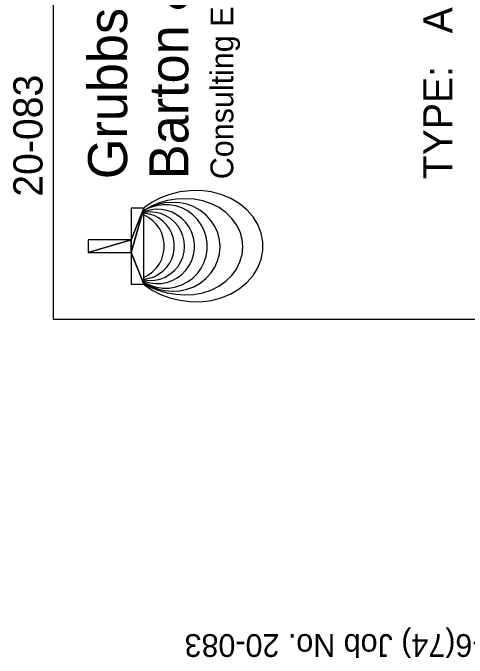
# Model space of a CAD drawing. Extents: x 1313964 to 1316843, y 2087046 to 2096619.
# Drawn here: x 1314172.79 to 1314180.68, y 2089867.54 to 2089878.76 of the extents above; entities that cross this region are included whole.
import ezdxf

# ---------------------------------------------------------------- set-up
doc = ezdxf.new("R2010")
doc.units = 0
doc.layers.add('B-Sub-Contour', color=7, linetype='Continuous')
doc.layers.add('Default', color=7, linetype='Continuous')

# ---------------------------------------------------------------- blocks, each defined once
blk = doc.blocks.new('DGRFC_GGHLOGO')
at = {"layer": 'Default'}
for points in [[(371581.68, 791230.32), (371581.68, 1050310.32), (295381.68, 1050310.32), (371581.68, 791230.32)], [(371581.68, 791230.32), (295381.68, 1050310.32), (295381.68, 791230.32), (371581.68, 791230.32)], [(295381.68, 791230.32), (104881.68, 791230.32), (104881.68, 715030.32), (295381.68, 791230.32)], [(295381.68, 791230.32), (104881.68, 715030.32), (562081.68, 715030.32), (295381.68, 791230.32)], [(295381.68, 791230.32), (562081.68, 715030.32), (371581.68, 791230.32), (295381.68, 791230.32)], [(562081.68, 715030.32), (562081.68, 791230.32), (371581.68, 791230.32), (562081.68, 715030.32)]]:
    blk.add_lwpolyline(points, close=True, dxfattribs=at)
for points in [[(105216.96, 715030.32), (100004.88, 709757.28), (68915.28, 666170.88), (42854.88, 615848.4), (22494.24, 560009.04), (8351.52, 500115.84), (792.48, 437662.32), (0, 374202.96), (7802.88, 311353.2), (23439.12, 250698), (46847.76, 193791.84), (77510.64, 142006.32), (114635.28, 96713.04), (157246.32, 59039.76), (204337.92, 29900.88), (254660.4, 10058.4), (306994.56, 0), (359968.8, 0), (412302.96, 10058.4), (462625.44, 29900.88), (509717.04, 59039.76), (552328.08, 96713.04), (589452.72, 142006.32), (620115.6, 193791.84), (643524.24, 250698), (659160.48, 311353.2), (666963.36, 374202.96), (666170.88, 437662.32), (658611.84, 500115.84), (644469.12, 560009.04), (624108.48, 615848.4), (598048.08, 666170.88), (566958.48, 709757.28), (561746.4, 715030.32)], [(111587.28, 715030.32), (108691.68, 711311.76), (85770.72, 670895.28), (67177.92, 625266.72), (53400.96, 575584.32), (44744.64, 523097.76), (41422.32, 469087.2), (42702.48, 414924.24), (52760.88, 362010.96), (69738.24, 311597.04), (93238.32, 264993.12), (122651.52, 223387.92), (157246.32, 187756.8), (196169.28, 159075.12), (238414.56, 137982.96), (282976.32, 125089.92), (328665.84, 120639.84), (374385.84, 124815.6), (419008.56, 137464.8), (461345.28, 158282.64), (500390.16, 186720.48), (535137.36, 222138.24), (564733.44, 263591.04), (588416.4, 310042.56), (605637.6, 360334.56), (615909.36, 413217.36), (618195.36, 467349.84), (615055.92, 521360.4), (606582.48, 573938.4), (592927.44, 623742.72), (574487.04, 669523.68), (551718.48, 710123.04), (547908.48, 715030.32)], [(113477.04, 715030.32), (111434.88, 712226.16), (91531.44, 674613.84), (76748.64, 633618.24), (67421.76, 590275.68), (63825.12, 545683.44), (65227.2, 500969.28), (74462.64, 457260.96), (90098.88, 415625.28), (111770.16, 377098.56), (138927.84, 342717.12), (170870.88, 313273.44), (206837.28, 289560), (245882.16, 272155.92), (287030.16, 261457.44), (329031.6, 257799.84), (371520.72, 261244.08), (412729.68, 271698.72), (451866, 288889.44), (487923.84, 312420), (520019.28, 341680.8), (547329.36, 375940.32), (569183.52, 414314.64), (585033.12, 455889.36), (594451.44, 499567.2), (596463.12, 544250.88), (593049.36, 588873.6), (583905.36, 632246.64), (569305.44, 673333.68), (549554.4, 711067.92), (546658.8, 715030.32)], [(117957.6, 715030.32), (116220.24, 712561.44), (98968.56, 677509.44), (87386.16, 640201.92), (81747.36, 601522.8), (82174.08, 562477.92), (88696.8, 523951.2), (101071.68, 486887.52), (119085.36, 452231.76), (142250.16, 420776.4), (170047.92, 393283.44), (201747.12, 370453.92), (236616.24, 352836.48), (273801.84, 340857.84), (312389.52, 334792.32), (351464.88, 334792.32), (390052.56, 340857.84), (427238.16, 352836.48), (462107.28, 370453.92), (493806.48, 393283.44), (521573.76, 420776.4), (544769.04, 452231.76), (562752.24, 486887.52), (575157.6, 523951.2), (581649.84, 562477.92), (582076.56, 601522.8), (576437.76, 640201.92), (564855.36, 677509.44), (547634.16, 712561.44), (545896.8, 715030.32)], [(124632.72, 715030.32), (123809.76, 713353.92), (113934.24, 680252.64), (109301.28, 646023.6), (110002.32, 611459.28), (116006.88, 577443.6), (127223.52, 544769.04), (143316.96, 514228.08), (163982.4, 486521.76), (188640.72, 462351.12), (216743.28, 442264.8), (247619.52, 426780.96), (280507.44, 416234.88), (314645.04, 410900.88), (349209.36, 410900.88), (383316.48, 416234.88), (416234.88, 426780.96), (447080.64, 442264.8), (475213.68, 462351.12), (499872, 486521.76), (520506.96, 514228.08), (536630.88, 544769.04), (547847.52, 577443.6), (553852.08, 611459.28), (554553.12, 646023.6), (549920.16, 680252.64), (540014.16, 713353.92), (539221.68, 715030.32)], [(130972.56, 715030.32), (130454.4, 713079.6), (127284.48, 680740.32), (129235.2, 648309.6), (136306.56, 616579.92), (148254.72, 586343.76), (164805.36, 558393.6), (185562.24, 533400), (210007.2, 511972.56), (237530.64, 494659.92), (267401.04, 481919.28), (298917.36, 474024.96), (331317.6, 471190.32), (363717.84, 473506.8), (395356.08, 480882.96), (425470.32, 493166.4), (453237.6, 510021.84), (478017.84, 531053.04), (499170.96, 555711.36), (516178.8, 583417.68), (528614.64, 613440.48), (536173.68, 645048.24), (538642.56, 677448.48), (535990.8, 709818.24), (534710.64, 715030.32)], [(135483.6, 715030.32), (135483.6, 714420.72), (140482.32, 683727.36), (150174.96, 654192.24), (164378.64, 626546.88), (182727.6, 601431.36), (204764.64, 579485.76), (229941.12, 561258.72), (257647.44, 547176.96), (287243.52, 537606.24), (317936.88, 532759.92), (349026.48, 532759.92), (379719.84, 537606.24), (409315.92, 547176.96), (437022.24, 561258.72), (462198.72, 579485.76), (484235.76, 601431.36), (502584.72, 626546.88), (516788.4, 654192.24), (526481.04, 683727.36), (531479.76, 714420.72), (531479.76, 715030.32)], [(146151.6, 715030.32), (160690.56, 687811.68), (179679.6, 662574.24), (202326.24, 640567.68), (228112.32, 622279.68), (256367.28, 608167.44), (286481.52, 598566.24), (317693.04, 593719.92), (349270.32, 593719.92), (380481.84, 598566.24), (410596.08, 608167.44), (438851.04, 622279.68), (464637.12, 640567.68), (487283.76, 662574.24), (506272.8, 687811.68), (520811.76, 715030.32)]]:
    blk.add_lwpolyline(points, dxfattribs=at)

msp = doc.modelspace()

# ---------------------------------------------------------------- linework, layer by layer
at = {"layer": 'B-Sub-Contour'}
msp.add_lwpolyline([(1314234.904, 2089873.434), (1314234.904, 2089916.306), (1314173.485, 2089916.306), (1314173.485, 2089873.434), (1314234.904, 2089873.434)], dxfattribs=at)

# ---------------------------------------------------------------- block references
at = {"layer": 'B-Sub-Contour', "xscale": 2.894891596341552e-06, "yscale": 2.894891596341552e-06, "rotation": 90}
msp.add_blockref('DGRFC_GGHLOGO', (1314177.133, 2089873.738), dxfattribs=at)

# ---------------------------------------------------------------- texts
at = {"layer": 'B-Sub-Contour'}
for s, height, rotation, p in [('TYPE:   Auger to 15 ft /Wash', 0.50899, 90, (1314180.428, 2089875.867)), ('Barton & Wyatt, Inc.', 0.67865, 90, (1314175.836, 2089875.867)), ('Grubbs, Hoskyn,', 0.67865, 90, (1314174.772, 2089875.867)), ('Consulting Engineers', 0.39588, 90, (1314176.617, 2089875.867)), ('20-083', 0.509, 90, (1314173.302, 2089875.563)), ('Form 108-6(74) Job No. 20-083', 0.39588, 180, (1314183.215, 2089867.961))]:
    msp.add_text(s, height=height, rotation=rotation, dxfattribs=at).set_placement(p)

doc.saveas('drawing.dxf')
